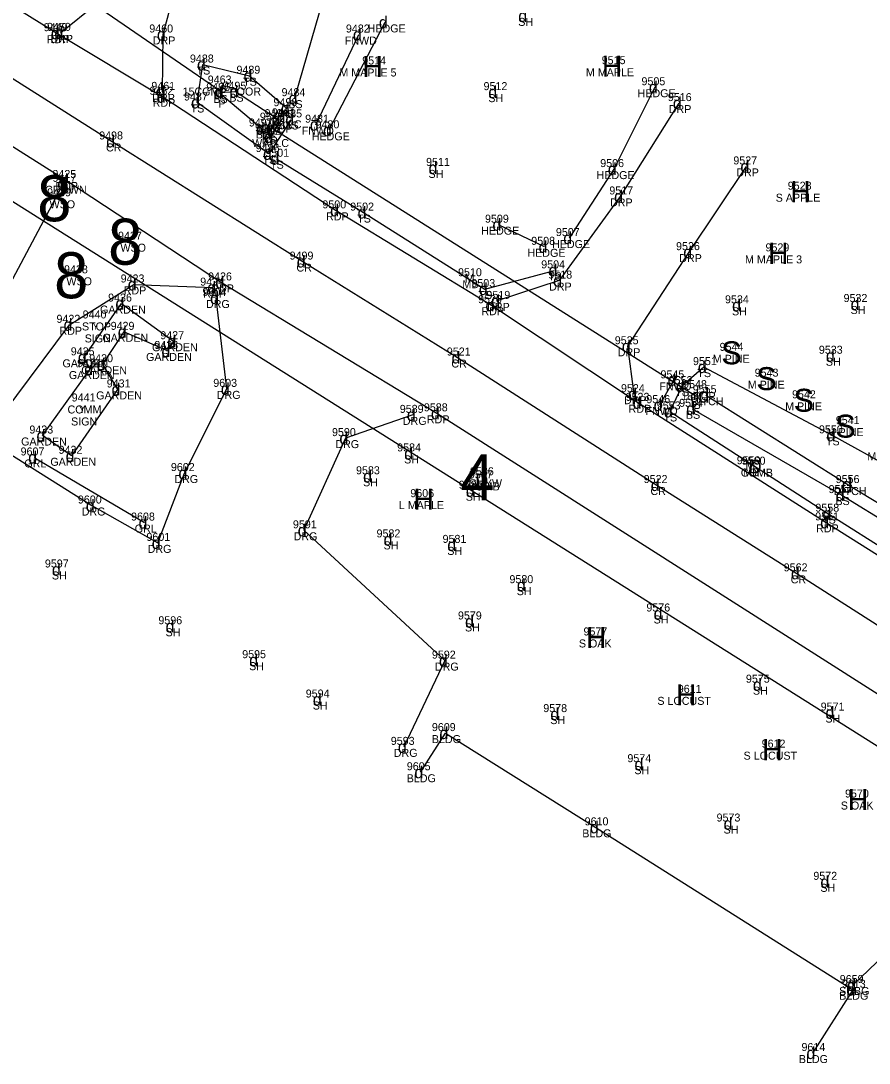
# Model space of a CAD drawing. Extents: x 69415 to 80913, y 7576 to 15059.
# Drawn here: x 78497.1 to 78709.2, y 12444.7 to 12705.2 of the extents above; entities that cross this region are included whole.
import ezdxf

# ---------------------------------------------------------------- set-up
doc = ezdxf.new("R2010")
doc.units = 0
for name, color, linetype in [('Level 11', 7, 'Continuous'), ('Level 12', 7, 'Continuous'), ('Level 13', 7, 'Continuous'), ('Level 14', 7, 'Continuous'), ('Level 15', 7, 'Continuous'), ('Level 16', 7, 'Continuous'), ('Level 43', 7, 'Continuous'), ('Level 46', 7, 'Continuous'), ('Level 47', 7, 'Continuous'), ('Level 48', 7, 'Continuous'), ('Level 59', 7, 'Continuous')]:
    doc.layers.add(name, color=color, linetype=linetype)

msp = doc.modelspace()

# ---------------------------------------------------------------- linework, layer by layer
at = {"layer": 'Level 11'}
for p, q in [((78476.35, 12720.6), (78506.07, 12702.12)), ((78537.51, 12720.21), (78532.6, 12701.8)), ((78506.98, 12702.21), (78516.11, 12709.53)), ((78506.07, 12702.12), (78532.55, 12686.23)), ((78532.6, 12701.8), (78532.45, 12687.45)), ((78532.55, 12686.23), (78575.89, 12657.83)), ((78661.58, 12684.65), (78646.89, 12661.31)), ((78483.76, 12680.88), (78508.24, 12665.43)), ((78664.19, 12647.39), (78678.46, 12668.82)), ((78508.24, 12665.43), (78547.21, 12639.82)), ((78646.89, 12661.31), (78631.65, 12640.28)), ((78575.89, 12657.83), (78614.73, 12634.12)), ((78648.82, 12623.86), (78664.19, 12647.39)), ((78547.21, 12639.82), (78601.1, 12607.1)), ((78631.65, 12640.28), (78616.18, 12635.2)), ((78509.26, 12629.23), (78525.3, 12639.31)), ((78525.3, 12639.31), (78545.19, 12638.52)), ((78548.58, 12613.21), (78545.88, 12635.92)), ((78614.73, 12634.12), (78651.53, 12609.72)), ((78492.67, 12606.99), (78509.26, 12629.23)), ((78650.37, 12611.88), (78648.82, 12623.86)), ((78537.98, 12592.17), (78548.58, 12613.21)), ((78651.53, 12609.72), (78698.4, 12579.84)), ((78595.09, 12606.71), (78578.22, 12600.9)), ((78601.1, 12607.1), (78775.93, 12495.84)), ((78578.22, 12600.9), (78567.79, 12577.85)), ((78491.36, 12598.8), (78514.82, 12584.05)), ((78531.3, 12574.71), (78537.98, 12592.17)), ((78514.82, 12584.05), (78531.3, 12574.71)), ((78698.4, 12579.84), (78741.21, 12552.71)), ((78567.79, 12577.85), (78603.11, 12545.28)), ((78603.11, 12545.28), (78592.83, 12523.72))]:
    msp.add_line(p, q, dxfattribs=at)
at = {"layer": 'Level 12'}
for p, q in [((78570.85, 12679.25), (78581.61, 12701.79)), ((78562.53, 12680.85), (78559.38, 12676.16)), ((78512.83, 12621.09), (78522.22, 12634.53)), ((78522.22, 12634.53), (78535.21, 12625.12)), ((78522.81, 12627.47), (78517.52, 12619.37)), ((78533.73, 12622.69), (78522.81, 12627.47)), ((78535.21, 12625.12), (78533.73, 12622.69)), ((78514.43, 12618.16), (78512.83, 12621.09)), ((78517.52, 12619.37), (78521.25, 12613.07)), ((78502.49, 12601.55), (78514.43, 12618.16)), ((78660.25, 12615.34), (78656.77, 12609.14)), ((78521.25, 12613.07), (78509.79, 12596.48)), ((78509.79, 12596.48), (78502.49, 12601.55)), ((78500.42, 12596.07), (78528.02, 12579.79))]:
    msp.add_line(p, q, dxfattribs=at)
at = {"layer": 'Level 13'}
for p, q in [((78596.96, 12517.37), (78603.23, 12527.16)), ((78603.23, 12527.16), (78640.85, 12503.6)), ((78640.85, 12503.6), (78705.07, 12463.01)), ((78705.07, 12463.01), (78694.97, 12447.18))]:
    msp.add_line(p, q, dxfattribs=at)
at = {"layer": 'Level 14'}
for p, q in [((78588.08, 12704.82), (78574.11, 12677.84)), ((78655.57, 12688.61), (78645.31, 12668.15)), ((78645.31, 12668.15), (78634.18, 12650.91)), ((78628.01, 12648.72), (78616.47, 12654.25))]:
    msp.add_line(p, q, dxfattribs=at)
at = {"layer": 'Level 15'}
for p, q in [((78265.18, 12804.76), (78754.05, 12497.03)), ((78753.41, 12510.83), (78705.11, 12464.18))]:
    msp.add_line(p, q, dxfattribs=at)
at = {"layer": 'Level 16'}
for p, q in [((78668.32, 12611.62), (78704.1, 12589.16)), ((78704.1, 12589.16), (78746.77, 12562.93))]:
    msp.add_line(p, q, dxfattribs=at)
at = {"layer": 'Level 48'}
for p, q in [((78573.46, 12713.66), (78565.52, 12685.88)), ((78468.06, 12707.84), (78519.93, 12675.06)), ((78541.13, 12684.8), (78542.62, 12694.29)), ((78542.62, 12694.29), (78554.26, 12691.49)), ((78554.26, 12691.49), (78563.59, 12683.38)), ((78550.77, 12687.49), (78546.75, 12687.18)), ((78546.75, 12687.18), (78557.36, 12678.3)), ((78561.28, 12680.63), (78550.77, 12687.49)), ((78559.12, 12671.93), (78541.13, 12684.8)), ((78558.89, 12677.04), (78561.28, 12680.63)), ((78564.7, 12680.56), (78559.12, 12671.93)), ((78519.93, 12675.06), (78567.55, 12645.03)), ((78560.98, 12670.74), (78582.76, 12657.28)), ((78507.71, 12664.47), (78491.4, 12634.02)), ((78582.76, 12657.28), (78613.06, 12638.16)), ((78567.55, 12645.03), (78606.27, 12621.05)), ((78613.06, 12638.16), (78630.5, 12642.84)), ((78606.27, 12621.05), (78656.05, 12589.17)), ((78667.8, 12618.65), (78662.29, 12613.89)), ((78699.95, 12601.59), (78667.8, 12618.65)), ((78662.29, 12613.89), (78659.32, 12607.57)), ((78659.32, 12607.57), (78698.97, 12582.01)), ((78664.91, 12608.23), (78702.28, 12586.66)), ((78725.58, 12587.41), (78699.95, 12601.59)), ((78656.05, 12589.17), (78691.1, 12567.09)), ((78702.28, 12586.66), (78745.29, 12560.15)), ((78698.97, 12582.01), (78742.33, 12554.42)), ((78691.1, 12567.09), (78730.87, 12541.54))]:
    msp.add_line(p, q, dxfattribs=at)
at = {"layer": 'Level 59'}
for p, q in [((78547.12, 12687.54), (78480.95, 12732.96)), ((78560.1, 12678.26), (78665.9, 12611.4))]:
    msp.add_line(p, q, dxfattribs=at)

# ---------------------------------------------------------------- texts
at = {"layer": 'Level 12'}
for p in [(78608.06, 12639.77), (78678.22, 12592.77)]:
    msp.add_text('M', height=2.2, dxfattribs=at).set_placement(p)
at = {"layer": 'Level 14'}
for s, height, p in [('H', 5.3, (78582.47, 12691.15)), ('H', 5.3, (78642.33, 12691.23)), ('H', 5.3, (78689.41, 12659.85)), ('H', 5.3, (78683.86, 12644.43)), ('S', 5.75, (78672.16, 12619.34)), ('S', 5.75, (78680.91, 12612.89)), ('S', 5.75, (78690.25, 12607.48)), ('S', 5.75, (78700.64, 12601.01)), ('H', 5.3, (78595.24, 12582.98)), ('H', 5.3, (78638.35, 12548.42)), ('H', 5.3, (78660.84, 12534.07)), ('H', 5.3, (78682.37, 12520.37)), ('H', 5.3, (78703.82, 12507.9))]:
    msp.add_text(s, height=height, dxfattribs=at).set_placement(p)
at = {"layer": 'Level 15'}
for s, height, p in [('8', 11.5, (78501.19, 12655.1)), ('8', 11.5, (78518.9, 12644.25)), ('8', 11.5, (78505.4, 12635.85)), ('4', 11.5, (78606.92, 12585.36)), ('D', 3.4, (78678.99, 12592.06)), ('D', 3.4, (78610.65, 12588.61))]:
    msp.add_text(s, height=height, dxfattribs=at).set_placement(p)
at = {"layer": 'Level 43'}
for p in [(78515.04, 12627.97), (78511.65, 12607.21)]:
    msp.add_text('Y', height=1.7, dxfattribs=at).set_placement(p)
at = {"layer": 'Level 46'}
for s, p in [('SH', (78621.43, 12703.95)), ('9449', (78502.8, 12702.62)), ('9450', (78503.63, 12702.71)), ('9460', (78529.2, 12702.3)), ('9482', (78578.35, 12702.29)), ('HEDGE', (78583.78, 12702.32)), ('RDP', (78503.56, 12699.62)), ('DRP', (78504.47, 12699.71)), ('DRP', (78530.08, 12699.3)), ('FNWD', (78578.07, 12699.29)), ('9488', (78539.36, 12694.79)), ('9514', (78582.43, 12694.3)), ('9515', (78642.29, 12694.38)), ('TS', (78541.03, 12691.79)), ('9489', (78550.99, 12691.99)), ('M MAPLE 5', (78576.72, 12691.3)), ('M MAPLE', (78638.34, 12691.38)), ('9461', (78529.71, 12687.95)), ('9496', (78543.44, 12687.68)), ('9463', (78543.81, 12689.54)), ('9495', (78547.51, 12687.99)), ('TS', (78552.67, 12688.99)), ('9512', (78612.76, 12687.89)), ('9505', (78652.24, 12689.11)), ('9462', (78529.25, 12686.73)), ('DRP', (78529.94, 12684.95)), ('15CGMP POOR', (78537.52, 12686.54)), ('9487', (78537.87, 12685.3)), ('BS', (78545.2, 12684.68)), ('BS', (78549.21, 12684.99)), ('9484', (78562.26, 12686.38)), ('SH', (78613.94, 12684.89)), ('HEDGE', (78651.27, 12686.11)), ('9516', (78658.83, 12685.15)), ('RDP', (78530.04, 12683.73)), ('TS', (78539.54, 12682.3)), ('P', (78546.49, 12683.54)), ('9490', (78560.25, 12683.88)), ('BS', (78563.96, 12683.38)), ('DRP', (78659.07, 12682.15)), ('9547', (78556.84, 12680.26)), ('9494', (78558.02, 12681.13)), ('9491', (78559.84, 12681.35)), ('9485', (78561.44, 12681.06)), ('TS', (78562, 12680.88)), ('9481', (78568.16, 12679.75)), ('9497', (78554.1, 12678.8)), ('9493', (78555.63, 12677.54)), ('18RCP', (78556.36, 12677.26)), ('WALLC', (78558.07, 12678.35)), ('BS', (78559.72, 12678.13)), ('TS', (78563.11, 12678.06)), ('FNWD', (78567.31, 12676.75)), ('9480', (78570.76, 12678.34)), ('9498', (78516.67, 12675.56)), ('BS', (78555.8, 12675.8)), ('9492', (78556.12, 12676.66)), ('BS', (78557.33, 12674.54)), ('P', (78559.48, 12674.26)), ('HEDGE', (78569.81, 12675.34)), ('CR', (78518.37, 12672.56)), ('WALLC', (78554.91, 12673.66)), ('9486', (78555.8, 12672.43)), ('TS', (78557.53, 12669.43)), ('9501', (78558.21, 12671.24)), ('9511', (78598.39, 12668.95)), ('9527', (78675.2, 12669.32)), ('TS', (78559.39, 12668.24)), ('9506', (78641.92, 12668.65)), ('9425', (78504.99, 12665.93)), ('9417', (78505.01, 12664.97)), ('SH', (78599, 12665.95)), ('HEDGE', (78641.01, 12665.65)), ('DRP', (78675.94, 12666.32)), ('CROWN', (78503.15, 12661.97)), ('9439', (78503.67, 12661.35)), ('RDP', (78505.73, 12662.93)), ('9517', (78644.2, 12661.81)), ('9528', (78688.8, 12663)), ('DRP', (78644.38, 12658.81)), ('S APPLE', (78685.79, 12660)), ('WSO', (78504.27, 12658.35)), ('9500', (78572.47, 12658.33)), ('9502', (78579.42, 12657.78)), ('RDP', (78573.38, 12655.33)), ('TS', (78581.17, 12654.78)), ('9509', (78613.12, 12654.75)), ('HEDGE', (78612.17, 12651.75)), ('9507', (78630.84, 12651.41)), ('9437', (78521.39, 12650.5)), ('9508', (78624.68, 12649.22)), ('HEDGE', (78629.88, 12648.41)), ('WSO', (78521.98, 12647.5)), ('9499', (78564.28, 12645.53)), ('HEDGE', (78623.72, 12646.22)), ('9526', (78660.88, 12647.89)), ('9529', (78683.24, 12647.58)), ('9504', (78627.17, 12643.34)), ('DRP', (78661.68, 12644.89)), ('M MAPLE 3', (78678.12, 12644.58)), ('9438', (78507.89, 12642.1)), ('9426', (78543.9, 12640.32)), ('CR', (78565.98, 12642.53)), ('9510', (78606.38, 12641.37)), ('TS', (78628.91, 12640.34)), ('9518', (78628.96, 12640.78)), ('WSO', (78508.48, 12639.1)), ('9423', (78522.04, 12639.81)), ('9424', (78541.93, 12639.02)), ('MB', (78607.47, 12638.37)), ('9503', (78609.72, 12638.66)), ('DRP', (78629.14, 12637.78)), ('RDP', (78522.79, 12636.81)), ('9604', (78542.49, 12636.42)), ('RDP', (78542.68, 12636.02)), ('RDP', (78544.7, 12637.32)), ('TS', (78611.47, 12635.66)), ('9519', (78613.48, 12635.7)), ('9436', (78518.91, 12635.03)), ('DRG', (78543.37, 12633.42)), ('9520', (78611.39, 12634.62)), ('DRP', (78613.67, 12632.7)), ('9534', (78673.12, 12634.6)), ('9532', (78702.76, 12634.92)), ('9440', (78512.54, 12630.82)), ('GARDEN', (78516.89, 12632.03)), ('RDP', (78612.22, 12631.62)), ('SH', (78674.87, 12631.6)), ('SH', (78704.51, 12631.92)), ('9422', (78506, 12629.73)), ('STOP', (78512.37, 12627.82)), ('9429', (78519.54, 12627.97)), ('RDP', (78506.75, 12626.73)), ('SIGN', (78513.05, 12624.82)), ('GARDEN', (78517.48, 12624.97)), ('9427', (78531.95, 12625.62)), ('GARDEN', (78529.88, 12622.62)), ('9428', (78530.47, 12623.19)), ('9525', (78645.56, 12624.36)), ('9544', (78671.77, 12622.72)), ('9435', (78509.57, 12621.59)), ('9430', (78514.18, 12619.87)), ('GARDEN', (78528.4, 12620.19)), ('9521', (78603.58, 12621.55)), ('DRP', (78646.31, 12621.36)), ('M PINE', (78670.06, 12619.72)), ('9533', (78696.58, 12621.99)), ('GARDEN', (78507.5, 12618.59)), ('9434', (78511.17, 12618.66)), ('GARDEN', (78512.19, 12616.87)), ('CR', (78604.7, 12618.55)), ('9551', (78665.11, 12619.15)), ('SH', (78698.33, 12618.99)), ('GARDEN', (78509.1, 12615.66)), ('9545', (78656.99, 12615.84)), ('9552', (78659.03, 12614.39)), ('TS', (78666.21, 12616.15)), ('9543', (78680.53, 12616.26)), ('9431', (78518.56, 12613.57)), ('9603', (78545.19, 12613.71)), ('9524', (78647.11, 12612.38)), ('FNWD', (78656.71, 12612.84)), ('9548', (78662.64, 12613.4)), ('9555', (78665.06, 12612.12)), ('M PINE', (78678.81, 12613.26)), ('9441', (78509.8, 12610.06)), ('GARDEN', (78515.92, 12610.57)), ('DRG', (78546.07, 12610.71)), ('DRP', (78647.86, 12609.38)), ('9523', (78648.27, 12610.22)), ('9546', (78653.46, 12609.64)), ('TS', (78660.7, 12611.39)), ('18RCP', (78662.16, 12610.4)), ('DITCH', (78664.56, 12609.12)), ('9542', (78689.87, 12610.85)), ('COMM', (78508.76, 12607.06)), ('9589', (78591.82, 12607.21)), ('9588', (78597.84, 12607.6)), ('RDP', (78649.02, 12607.22)), ('FNWD', (78653.24, 12606.64)), ('9553', (78656.06, 12608.07)), ('9554', (78661.65, 12608.73)), ('P', (78665.27, 12607.4)), ('M PINE', (78688.15, 12607.85)), ('SIGN', (78509.65, 12604.06)), ('DRG', (78592.58, 12604.21)), ('RDP', (78598.59, 12604.6)), ('TS', (78657.73, 12605.07)), ('BS', (78663.35, 12605.73)), ('9541', (78700.82, 12604.39)), ('9433', (78499.23, 12602.05)), ('9590', (78574.87, 12601.4)), ('9550', (78696.6, 12602.09)), ('M PINE', (78698.54, 12601.39)), ('GARDEN', (78497.16, 12599.05)), ('TS', (78698.36, 12599.09)), ('9607', (78497.03, 12596.57)), ('9432', (78506.53, 12596.98)), ('DRG', (78575.71, 12598.4)), ('9584', (78591.16, 12597.57)), ('GRL', (78497.96, 12593.57)), ('GARDEN', (78504.46, 12593.98)), ('SH', (78592.91, 12594.57)), ('9559', (78676.06, 12594.37)), ('9560', (78677.29, 12594.26)), ('M PINE', (78708.71, 12595.33)), ('9602', (78534.6, 12592.67)), ('9583', (78580.88, 12591.86)), ('9587', (78609.09, 12590.81)), ('9586', (78609.36, 12591.61)), ('COMB', (78677.07, 12591.26)), ('MB', (78677.63, 12591.37)), ('DRG', (78535.47, 12589.67)), ('SH', (78582.63, 12588.86)), ('9585', (78606.56, 12588.25)), ('GUYW', (78609.06, 12588.61)), ('9522', (78652.79, 12589.67)), ('9556', (78700.79, 12589.66)), ('9606', (78594.45, 12586.14)), ('COMB', (78608.74, 12587.81)), ('CR', (78654.48, 12586.67)), ('9557', (78699.02, 12587.16)), ('DITCH', (78700.34, 12586.66)), ('9600', (78511.35, 12584.55)), ('L MAPLE', (78591.59, 12583.14)), ('SH', (78608.31, 12585.25)), ('BS', (78700.72, 12584.16)), ('DRG', (78512.31, 12581.55)), ('9561', (78695.66, 12580.34)), ('9558', (78695.71, 12582.51)), ('9608', (78524.64, 12580.29)), ('9591', (78565.1, 12578.35)), ('TS', (78697.38, 12579.51)), ('GRL', (78525.57, 12577.29)), ('9601', (78528.49, 12575.21)), ('DRG', (78565.28, 12575.35)), ('9582', (78586.01, 12576.08)), ('RDP', (78695.89, 12577.34)), ('SH', (78587.76, 12573.08)), ('9581', (78602.51, 12574.71)), ('DRG', (78528.79, 12572.21)), ('SH', (78603.69, 12571.71)), ('9597', (78503.1, 12568.56)), ('9562', (78687.79, 12567.59)), ('SH', (78504.85, 12565.56)), ('9580', (78619.23, 12564.64)), ('CR', (78689.53, 12564.59)), ('SH', (78621.06, 12561.64)), ('9576', (78653.46, 12557.56)), ('9596', (78531.47, 12554.37)), ('9579', (78606.36, 12555.57)), ('SH', (78655.27, 12554.56)), ('SH', (78608.12, 12552.57)), ('SH', (78533.27, 12551.37)), ('9577', (78637.74, 12551.57)), ('S OAK', (78636.59, 12548.57)), ('9595', (78552.42, 12545.89)), ('9592', (78599.85, 12545.78)), ('SH', (78554.16, 12542.89)), ('DRG', (78600.6, 12542.78)), ('9575', (78678.34, 12539.76)), ('9594', (78568.31, 12536.05)), ('9611', (78661.31, 12537.22)), ('SH', (78680.09, 12536.76)), ('S LOCUST', (78656.22, 12534.22)), ('SH', (78570.06, 12533.05)), ('9578', (78627.69, 12532.41)), ('9571', (78697.03, 12532.79)), ('SH', (78629.44, 12529.41)), ('SH', (78698.21, 12529.79)), ('9609', (78599.84, 12527.66)), ('9593', (78589.57, 12524.22)), ('BLDG', (78599.83, 12524.66)), ('9612', (78682.28, 12523.52)), ('DRG', (78590.32, 12521.22)), ('S LOCUST', (78677.76, 12520.52)), ('9605', (78593.57, 12517.87)), ('9574', (78648.72, 12519.89)), ('SH', (78650.47, 12516.89)), ('BLDG', (78593.55, 12514.87)), ('9570', (78703.12, 12511.05)), ('S OAK', (78702.06, 12508.05)), ('9573', (78671.01, 12505.05)), ('9610', (78638.03, 12504.1)), ('BLDG', (78637.44, 12501.1)), ('SH', (78672.76, 12502.05)), ('9572', (78695.2, 12490.48)), ('SH', (78696.95, 12487.48)), ('9659', (78701.8, 12464.68)), ('9613', (78702.33, 12463.51)), ('SUBG', (78701.64, 12461.68)), ('BLDG', (78701.66, 12460.51)), ('9614', (78692.23, 12447.68)), ('BLDG', (78691.57, 12444.68))]:
    msp.add_text(s, height=2, dxfattribs=at).set_placement(p)
at = {"layer": 'Level 47'}
for height, p in [(3, (78621.44, 12704.95)), (3, (78586.58, 12703.32)), (3, (78504.57, 12700.62)), (3, (78505.48, 12700.71)), (3, (78531.1, 12700.3)), (3, (78580.11, 12700.29)), (3, (78541.12, 12692.79)), (3, (78552.76, 12689.99)), (3, (78545.62, 12686.04)), (3, (78654.07, 12687.11)), (3, (78530.95, 12685.95)), (3, (78531.05, 12684.73)), (3, (78545.25, 12685.68)), (3, (78549.27, 12685.99)), (3, (78564.02, 12684.38)), (3, (78613.95, 12685.89)), (3, (78539.63, 12683.3)), (3, (78562.09, 12681.88)), (3, (78660.08, 12683.15)), (3, (78559.78, 12679.13)), (3, (78561.03, 12679.35)), (3, (78563.2, 12679.06)), (3, (78555.86, 12676.8)), (3, (78558.6, 12676.76)), (3, (78569.35, 12677.75)), (3, (78572.61, 12676.34)), (3, (78518.43, 12673.56)), (3, (78557.39, 12675.54)), (3, (78557.88, 12674.66)), (3, (78557.62, 12670.43)), (3, (78559.48, 12669.24)), (3, (78599.01, 12666.95)), (3, (78643.81, 12666.65)), (3, (78676.96, 12667.32)), (3, (78506.21, 12662.97)), (3, (78506.74, 12663.93)), (3, (78645.39, 12659.81)), (3, (78574.39, 12656.33)), (3, (78581.26, 12655.78)), (3, (78614.97, 12652.75)), (3, (78626.51, 12647.22)), (3, (78632.68, 12649.41)), (3, (78662.69, 12645.89)), (3, (78566.05, 12643.53)), (3, (78629, 12641.34)), (3, (78523.8, 12637.81)), (3, (78543.69, 12637.02)), (3, (78545.71, 12638.32)), (3, (78611.56, 12636.66)), (3, (78630.15, 12638.78)), (3, (78544.38, 12634.42)), (3, (78520.72, 12633.03)), (3, (78613.23, 12632.62)), (3, (78614.68, 12633.7)), (3, (78674.88, 12632.6)), (3, (78704.52, 12632.92)), (3, (78507.76, 12627.73)), (3, (78521.31, 12625.97)), (3, (78533.71, 12623.62)), (3, (78532.23, 12621.19)), (3, (78647.32, 12622.36)), (3, (78511.33, 12619.59)), (3, (78604.77, 12619.55)), (3, (78698.34, 12619.99)), (3, (78512.93, 12616.66)), (3, (78516.02, 12617.87)), (3, (78666.3, 12617.15)), (3, (78658.75, 12613.84)), (3, (78519.75, 12611.57)), (3, (78547.08, 12611.71)), (3, (78660.79, 12612.39)), (3.7, (78666.47, 12609.77)), (3, (78648.87, 12610.38)), (3, (78650.03, 12608.22)), (3, (78664.4, 12609.9)), (3, (78599.6, 12605.6)), (3, (78655.27, 12607.64)), (3, (78657.82, 12606.07)), (3, (78663.41, 12606.73)), (3, (78593.59, 12605.21)), (3, (78500.99, 12600.05)), (3, (78698.45, 12600.09)), (3, (78576.72, 12599.4)), (3, (78508.29, 12594.98)), (3, (78592.92, 12595.57)), (3, (78498.92, 12594.57)), (3, (78536.48, 12590.67)), (3, (78582.64, 12589.86)), (3, (78654.55, 12587.67)), (3.7, (78702.25, 12587.31)), (3, (78608.32, 12586.25)), (3, (78700.78, 12585.16)), (3, (78513.32, 12582.55)), (3, (78697.47, 12580.51)), (3, (78526.52, 12578.29)), (3, (78696.9, 12578.34)), (3, (78566.29, 12576.35)), (3, (78587.77, 12574.08)), (3, (78529.8, 12573.21)), (3, (78603.7, 12572.71)), (3, (78504.86, 12566.56)), (3, (78689.6, 12565.59)), (3, (78621.08, 12562.64)), (3, (78608.13, 12553.57)), (3, (78655.28, 12555.56)), (3, (78533.28, 12552.37)), (3, (78554.18, 12543.89)), (3, (78601.61, 12543.78)), (3, (78680.1, 12537.76)), (3, (78570.07, 12534.05)), (3, (78629.45, 12530.41)), (3, (78698.22, 12530.79)), (3, (78601.73, 12525.66)), (3, (78591.33, 12522.22)), (3, (78650.48, 12517.89)), (3, (78595.46, 12515.87)), (3, (78639.35, 12502.1)), (3, (78672.77, 12503.05)), (3, (78696.96, 12488.48)), (3, (78703.61, 12462.68)), (3, (78703.57, 12461.51)), (3, (78693.47, 12445.68))]:
    msp.add_text('d', height=height, dxfattribs=at).set_placement(p)

doc.saveas('drawing.dxf')
